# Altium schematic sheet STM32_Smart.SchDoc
size A3
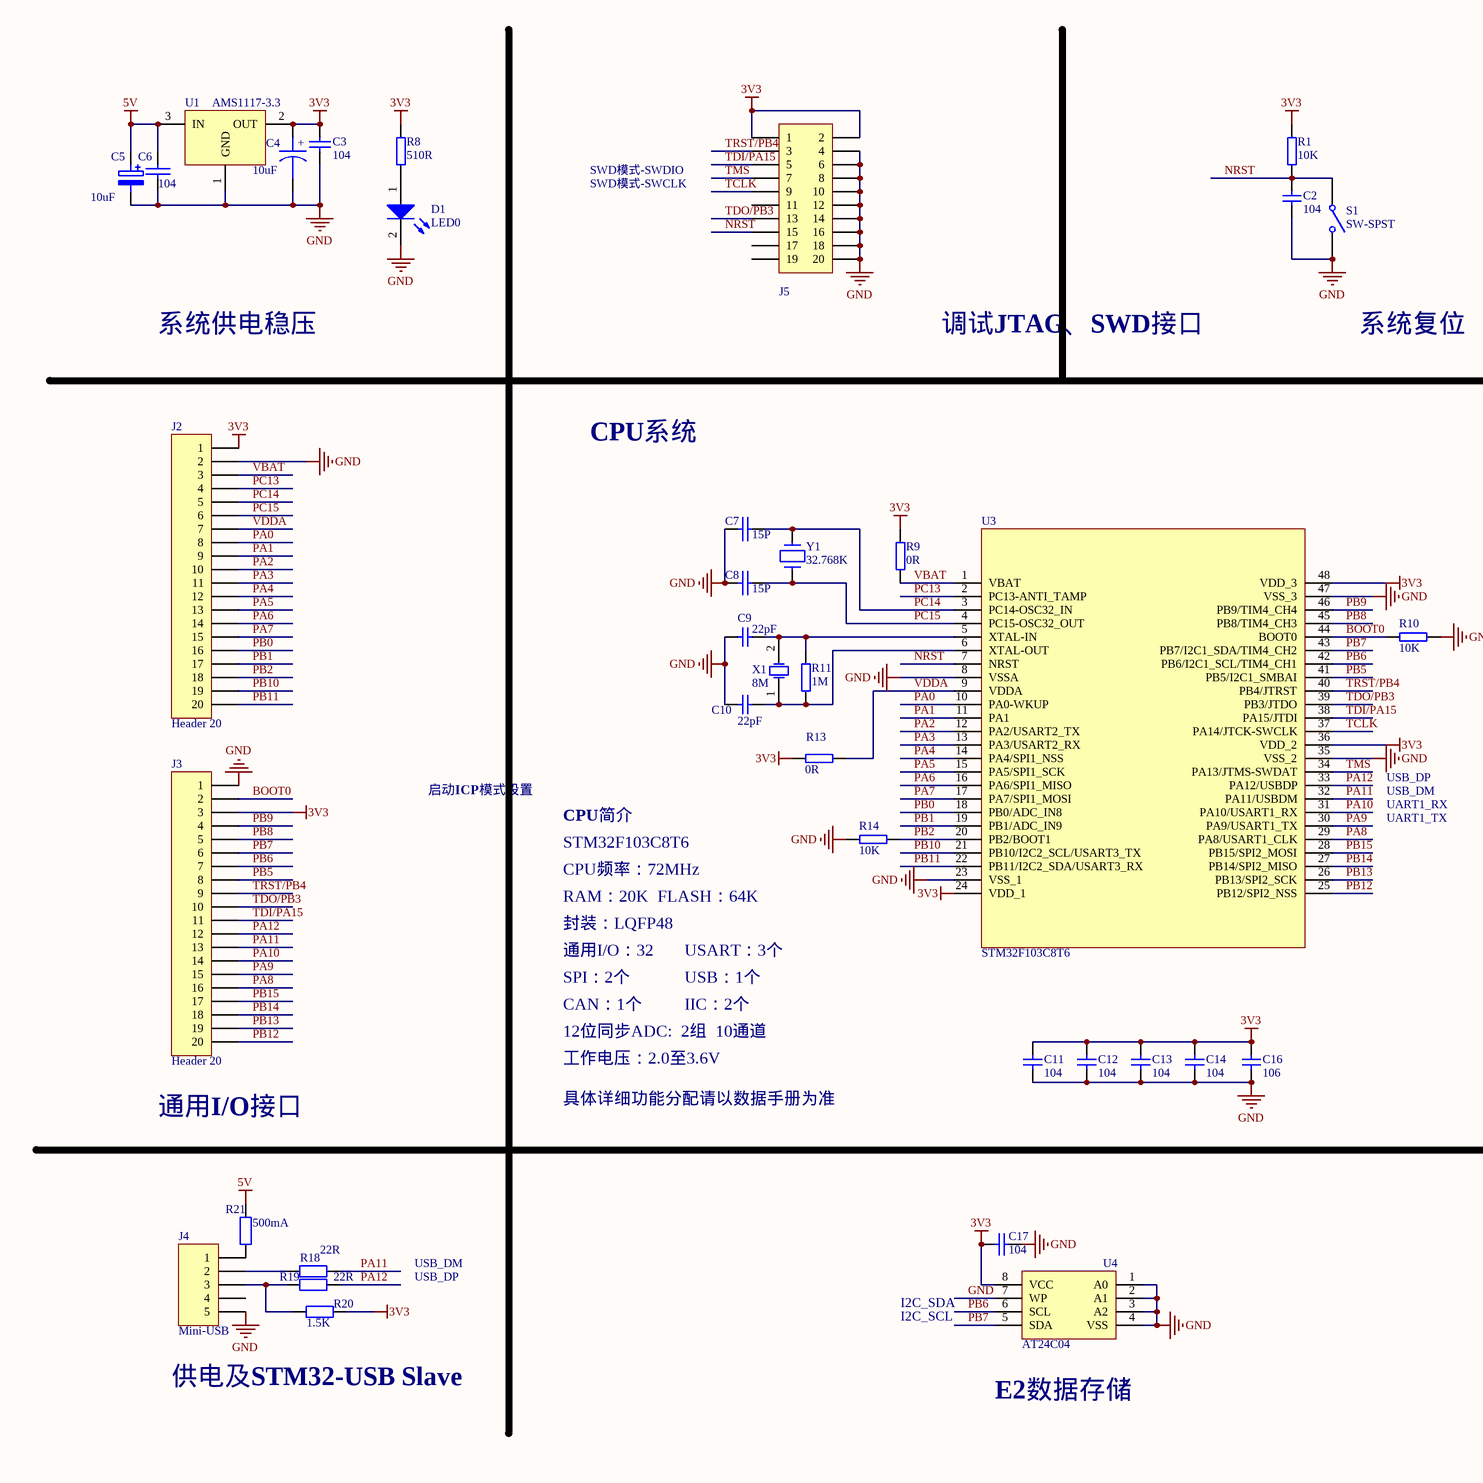
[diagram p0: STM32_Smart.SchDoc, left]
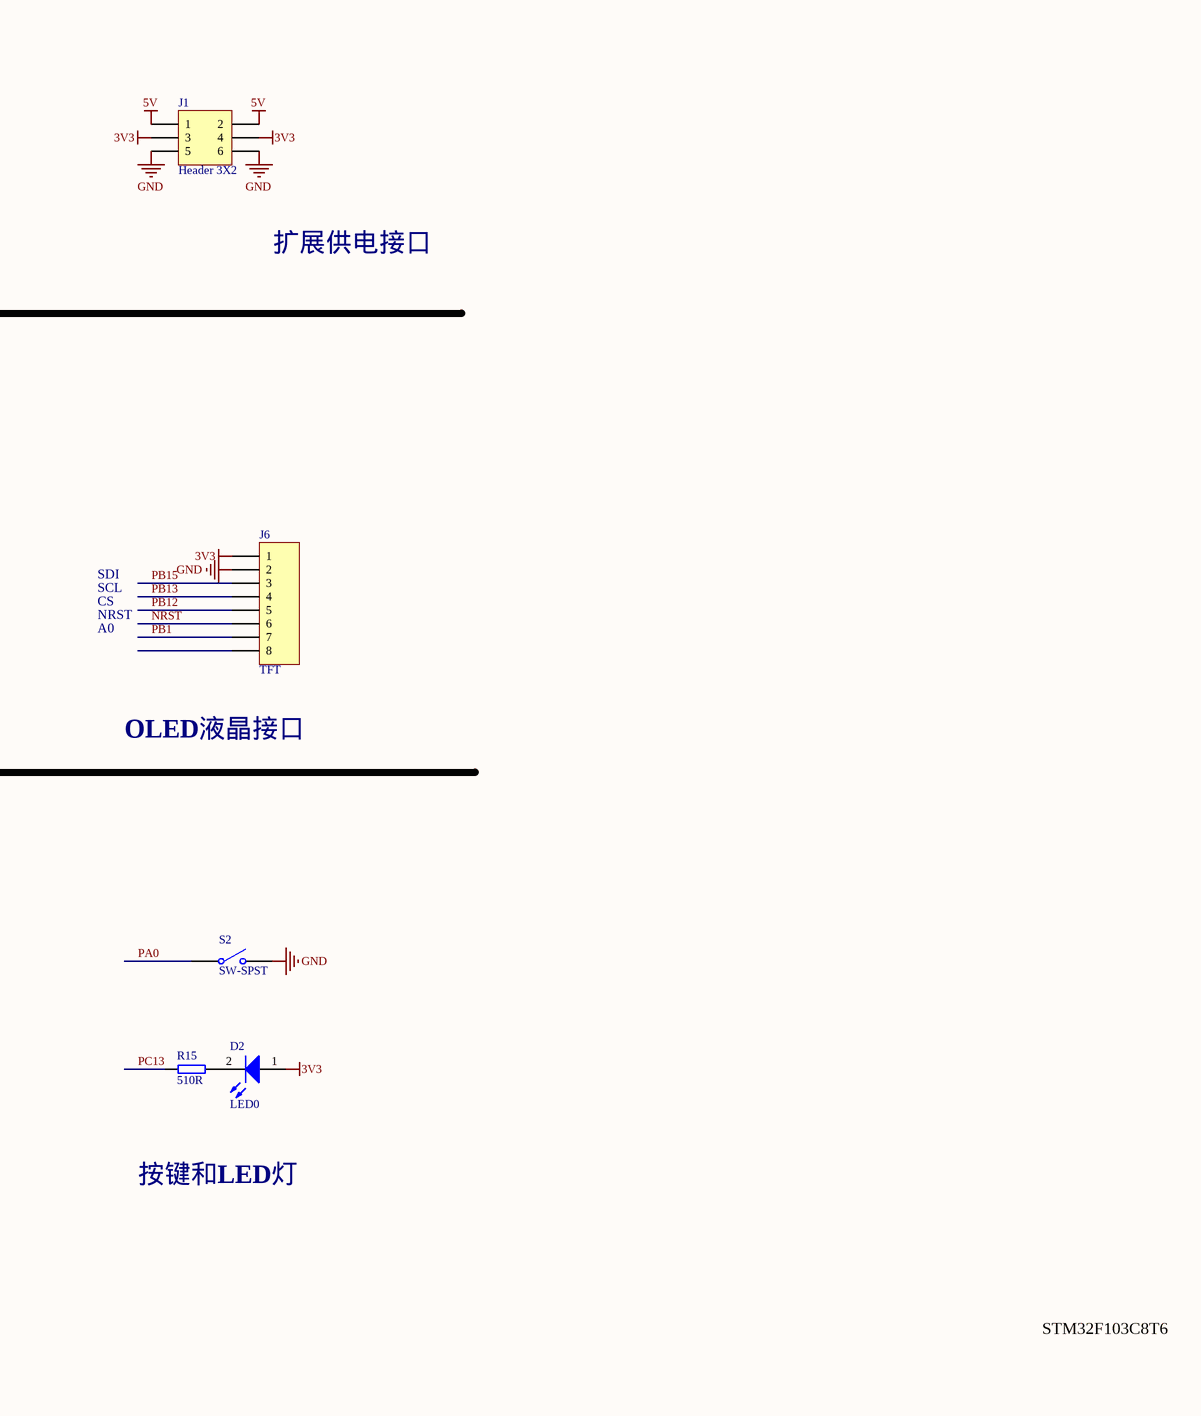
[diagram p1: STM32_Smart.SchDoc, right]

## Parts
C2  104  [RC0603]
C3  104  [RC0603]
C4  10uF  [RC0805]
C5  10uF  [RC0805]
C6  104  [RC0603]
C7  15P  [RC0603]
C8  15P  [RC0603]
C9  22pF  [RC0603]
C10  22pF  [RC0603]
C11  104  [RC0603]
C12  104  [RC0603]
C13  104  [RC0603]
C14  104  [RC0603]
C16  106  [RC0805]
C17  104  [RC0603]
D1  LED0  [LED0805]
D2  LED0  [LED0805]
J1  Header 3X2  [IDE3X2-2.54]
J2  Header 20  [HDR1X20]
J3  Header 20  [HDR1X20]
J4  Mini-USB  [mini_USB]
J5  (no value)  [JTAG20P]
J6  TFT  [HDR1X8]
R1  10K  [RC0603]
R8  510R  [RC0603]
R9  0R  [RC0603]
R10  10K  [RC0603]
R11  1M  [RC0603]
R13  0R  [RC0603]
R14  10K  [RC0603]
R15  510R  [RC0603]
R18  22R  [RC0603]
R19  22R  [RC0603]
R20  1.5K  [RC0603]
R21  500mA  [RC0805]
S1  SW-SPST  [SMT-KEY]
S2  SW-SPST  [SMT-KEY]
U1  AMS1117-3.3  [SOT223]
U3  STM32F103C8T6  [LQFP48]
U4  AT24C04  [SOIC-8P]
X1  8M  [SMD49S]
Y1  32.768K  [JZ32768]

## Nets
3V3: C3.1 C4.1 C11.1 C12.1 C13.1 C14.1 C16.1 C17.2 D2.1(A) J1.3 J1.4 J2.1 J3.3 J5.1 J5.2 J6.1 R1.2 R8.2 R9.2 R13.2 R20.1 U1.2(OUT) U3.24(VDD_1) U3.36(VDD_2) U3.48(VDD_3) U4.8(VCC)
5V: C5.1 C6.1 J1.1 J1.2 R21.1 U1.3(IN)
GND: C2.2 C3.2 C4.2 C5.2 C6.2 C7.1 C8.1 C9.2 C10.2 C11.2 C12.2 C13.2 C14.2 C16.2 C17.1 D1.2(K) J1.5 J1.6 J2.2 J3.1 J4.5 J5.4 J5.6 J5.8 J5.10 J5.12 J5.14 J5.16 J5.18 J5.20 J6.2 R10.1 R14.2 S1.2(NO) S2.2(NO) U1.1(GND) U3.8(VSSA) U3.23(VSS_1) U3.35(VSS_2) U3.47(VSS_3) U4.1(A0) U4.2(A1) U4.3(A2) U4.4(VSS) U4.7(WP)
BOOT0: J3.2 R10.2 U3.44(BOOT0)
NRST: C2.1 J5.15 J6.6 R1.1 S1.1(COMMON) U3.7(NRST)
PA0: J2.8 S2.1(COMMON) U3.10(PA0-WKUP)
PA1: J2.9 U3.11(PA1)
PA2: J2.10 U3.12(PA2/USART2_TX)
PA3: J2.11 U3.13(PA3/USART2_RX)
PA4: J2.12 U3.14(PA4/SPI1_NSS)
PA5: J2.13 U3.15(PA5/SPI1_SCK)
PA6: J2.14 U3.16(PA6/SPI1_MISO)
PA7: J2.15 U3.17(PA7/SPI1_MOSI)
PA8: J3.16 U3.29(PA8/USART1_CLK)
PA9: J3.15 U3.30(PA9/USART1_TX)
PA10: J3.14 U3.31(PA10/USART1_RX)
PA11: J3.13 R18.1 U3.32(PA11/USBDM)
PA12: J3.12 R19.1 U3.33(PA12/USBDP)
PB0: J2.16 U3.18(PB0/ADC_IN8)
PB1: J2.17 J6.7 U3.19(PB1/ADC_IN9)
PB2: J2.18 R14.1 U3.20(PB2/BOOT1)
PB5: J3.8 U3.41(PB5/I2C1_SMBAI)
PB6: J3.7 U3.42(PB6/I2C1_SCL/TIM4_CH1) U4.6(SCL)
PB7: J3.6 U3.43(PB7/I2C1_SDA/TIM4_CH2) U4.5(SDA)
PB8: J3.5 U3.45(PB8/TIM4_CH3)
PB9: J3.4 U3.46(PB9/TIM4_CH4)
PB10: J2.19 U3.21(PB10/I2C2_SCL/USART3_TX)
PB11: J2.20 U3.22(PB11/I2C2_SDA/USART3_RX)
PB12: J3.20 J6.5 U3.25(PB12/SPI2_NSS)
PB13: J3.19 J6.4 U3.26(PB13/SPI2_SCK)
PB14: J3.18 U3.27(PB14/SPI2_MISO)
PB15: J3.17 J6.3 U3.28(PB15/SPI2_MOSI)
PC13: J2.4 R15.1 U3.2(PC13-ANTI_TAMP)
PC14: C7.2 J2.5 U3.3(PC14-OSC32_IN) Y1.2
PC15: C8.2 J2.6 U3.4(PC15-OSC32_OUT) Y1.1
TCLK: J5.9 U3.37(PA14/JTCK-SWCLK)
TDI/PA15: J3.11 J5.5 U3.38(PA15/JTDI)
TDO/PB3: J3.10 J5.13 U3.39(PB3/JTDO)
TMS: J5.7 U3.34(PA13/JTMS-SWDAT)
TRST/PB4: J3.9 J5.3 U3.40(PB4/JTRST)
VBAT: J2.3 R9.1 U3.1(VBAT)
VDDA: J2.7 R13.1 U3.9(VDDA)
NetC9_1: C9.1 R11.2 U3.5(XTAL-IN) X1.2
NetC10_1: C10.1 R11.1 U3.6(XTAL-OUT) X1.1
NetD1_1: D1.1(A) R8.1
NetD2_2: D2.2(K) R15.2
NetJ4_1: J4.1 R21.2
NetJ4_2: J4.2 R18.2
NetJ4_3: J4.3 R19.2 R20.2

Not connected (* = marked no-connect by the designer): J4 4; J5 11 17 19; J6 8

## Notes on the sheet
- SWD模式-SWCLK
- SWD模式-SWDIO
- 系统供电稳压
- (near J5) 调试JTAG、SWD接口
- 系统复位
- 扩展供电接口
- CPU系统
- SDI
- SCL
- CS
- NRST
- A0
- 启动ICP模式设置
- CPU简介
- UART1_TX
- UART1_RX
- USB_DM
- USB_DP
- OLED液晶接口
- STM32F103C8T6
- RAM：20K
- CPU频率：72MHz
- FLASH：64K
- 封装：LQFP48
- 通用I/O：32
- USART：3个
- CAN：1个
- 12位同步ADC:  2组  10通道
- SPI：2个
- USB：1个
- IIC：2个
- 工作电压：2.0至3.6V
- 具体详细功能分配请以数据手册为准
- (near J3) 通用I/O接口
- I2C_SDA
- 按键和LED灯
- I2C_SCL
- 供电及STM32-USB Slave
- (near U4) E2数据存储

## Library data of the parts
C2 C11-C14 C16 = CAP1: Capacitor; Tolerate: 50V; Value: 100nF; TOL: 10%; ERP: 0103020075; PCB_Layout: Top Layer SMC
C3 C17 = Cap: Capacitor
C4 = CAPACITOR POL: Capacitor
C5 = ELECTRO2
C6 = CAP: Capacitor
C7 C8 = CAP
C9 C10 = CAP1: Capacitor; Tolerate: 50V; Value: 20pF; TOL: 2%; ERP: 0103020090; PCB_Layout: Top Layer SMC
D1 D2 = LED0: Typical INFRARED GaAs LED
J1 = Header 3X2: Header, 3-Pin, Dual row
J2 J3 = Header 20: Header, 20-Pin
J4 = Header 5: Header, 5-Pin
J5 = Header 10X2H: Header, 10-Pin, Dual row, Right Angle
J6 = Header 8: Header, 8-Pin
R1 R8-R11 R13-R15 = R
R18-R21 = Res2: Resistor
S1 S2 = SW-SPST: Single-Pole, Single-Throw Switch
U1 = LT1085CM-3.3
U4 = EPROM
X1 = XTAL_SMD: Crystal Oscillator; ERP: 0103040021; Value: 8MHz; TOL: ±20ppm; Tolerate: ROSON -20_+70 20pf; PCB_Layout: Top Layer SMC
Y1 = CRYSTAL: 晶振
